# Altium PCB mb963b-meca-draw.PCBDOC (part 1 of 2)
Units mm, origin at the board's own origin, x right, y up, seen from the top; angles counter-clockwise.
Board outline 55.97 x 112.25 mm, 2 copper layers (Top, Bottom), stack 0.323 mm thick; 137 components, 131 nets, 523 pads, 261 vias.
Unrouted connection lines stored in the file: 17.
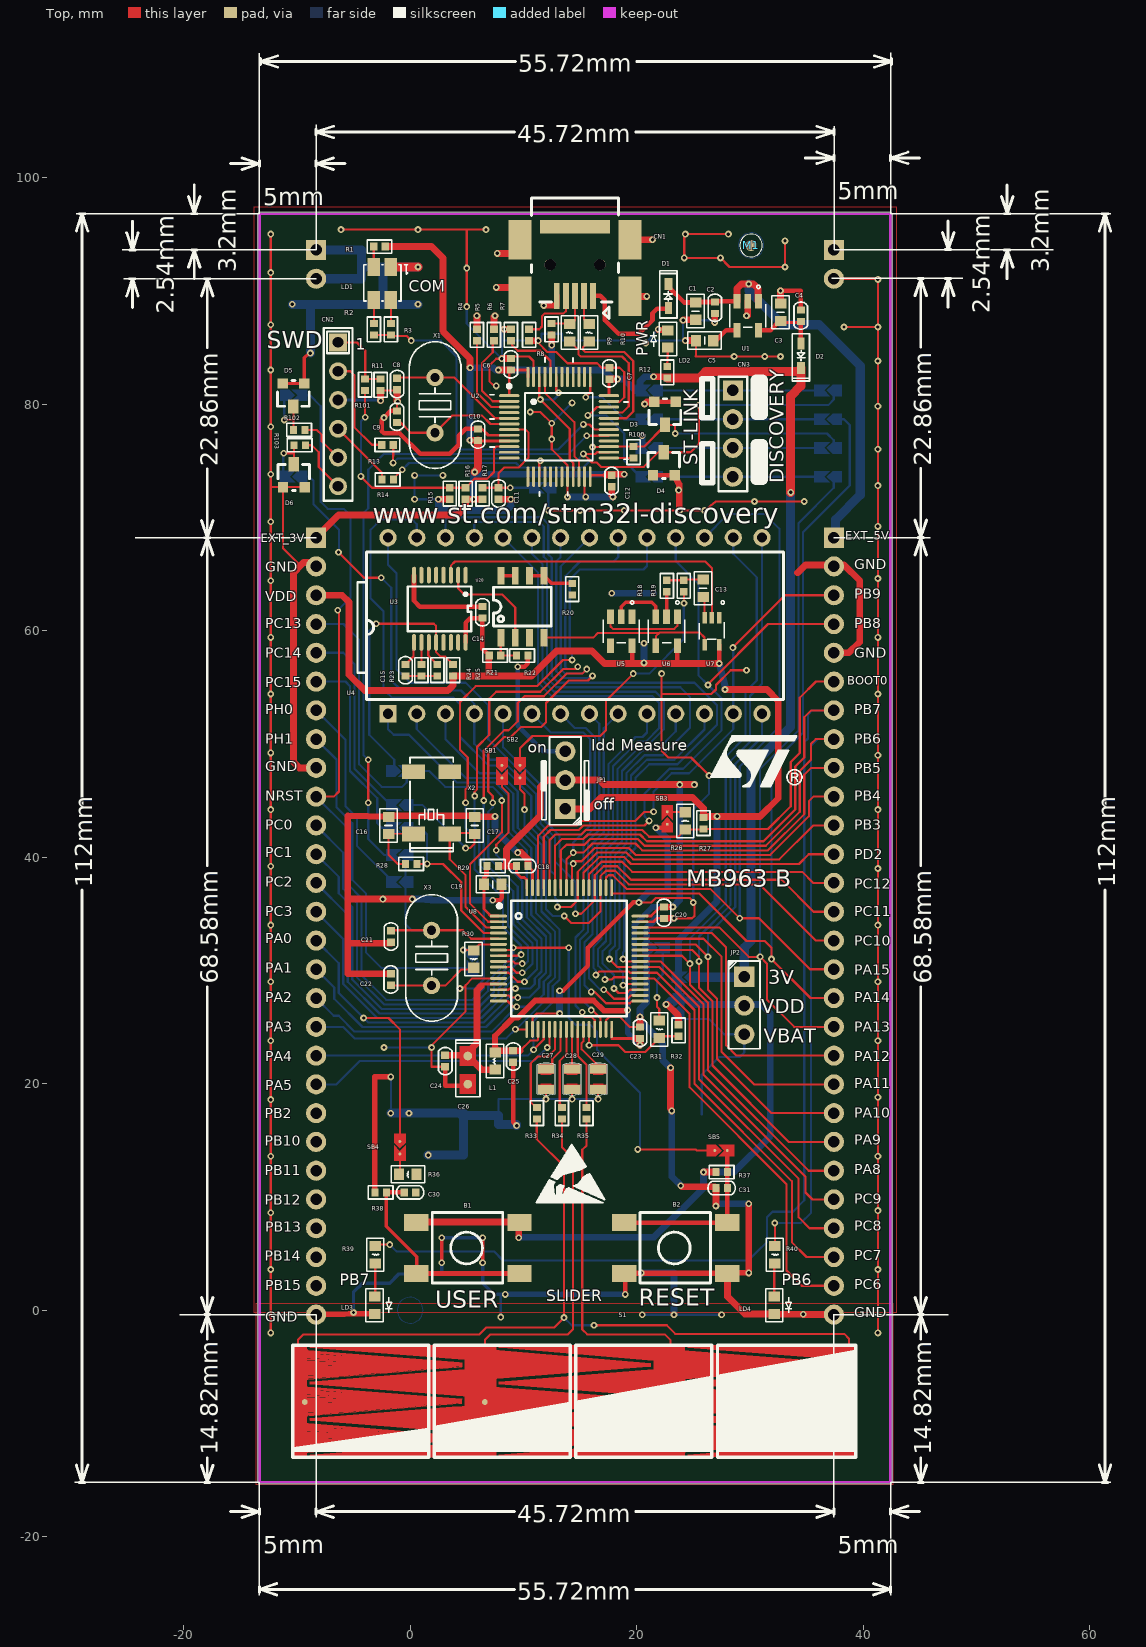
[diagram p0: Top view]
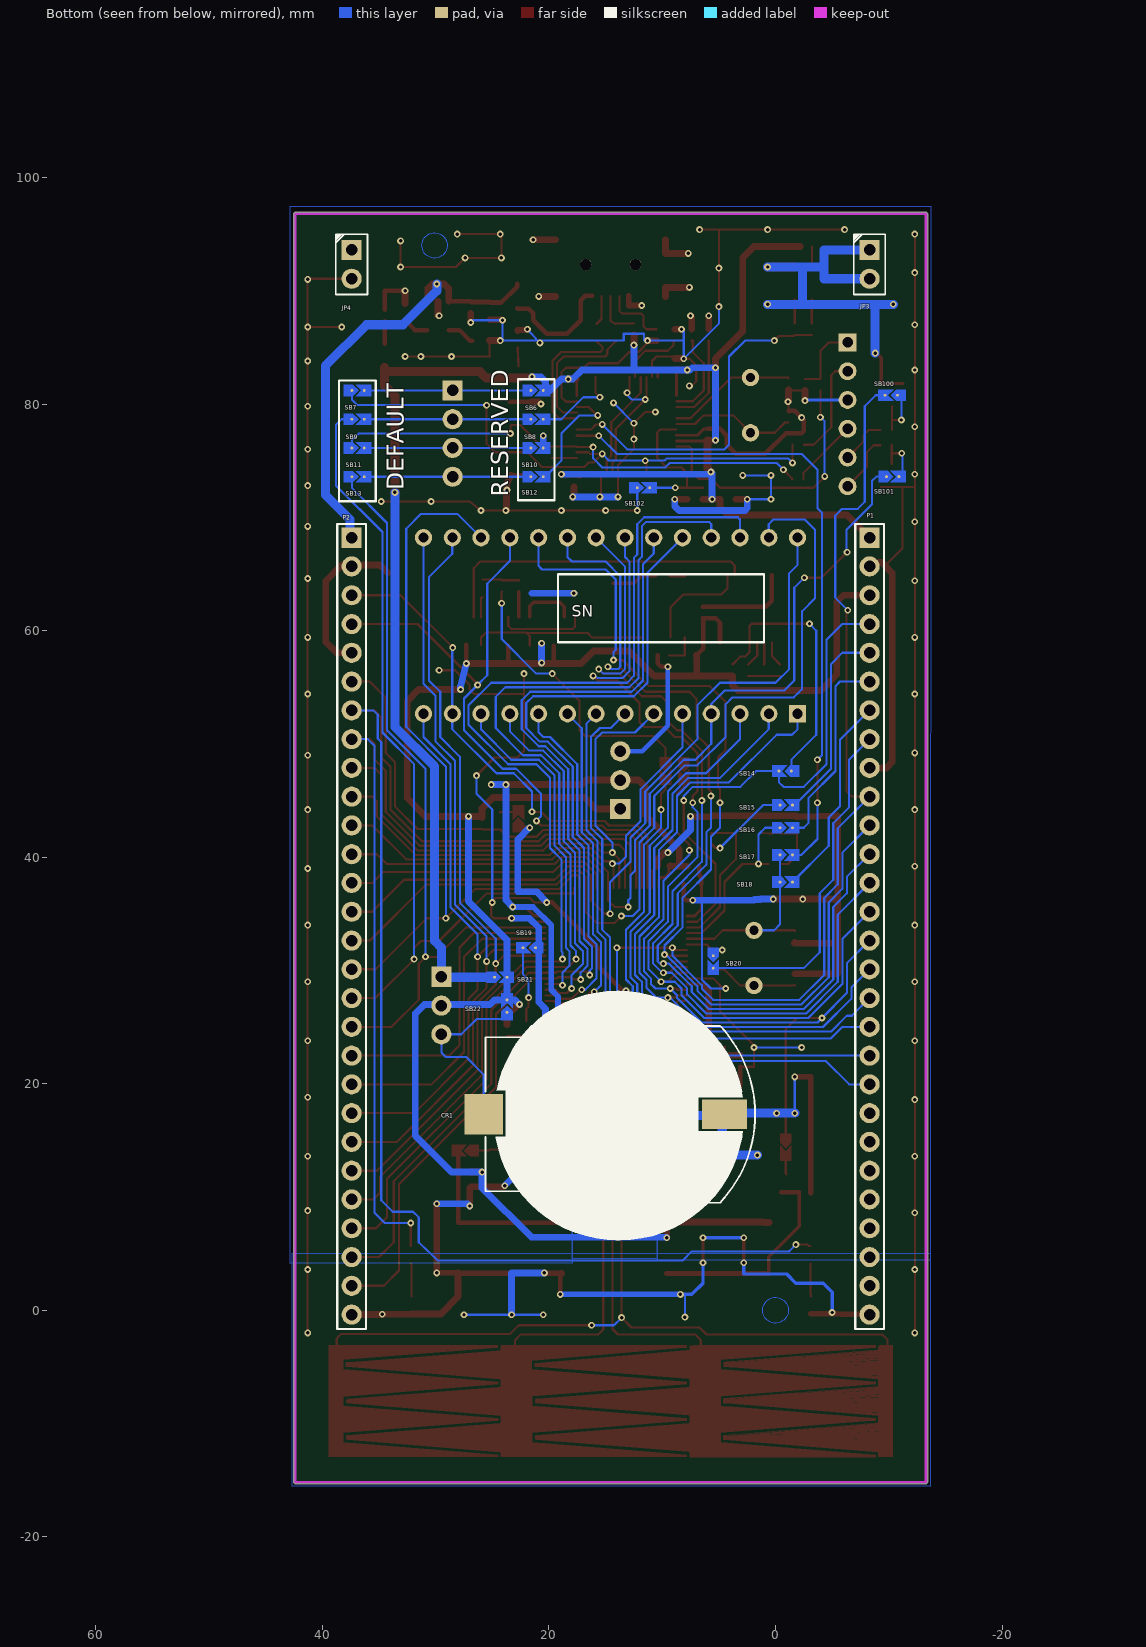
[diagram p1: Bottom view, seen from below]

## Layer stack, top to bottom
Top: signal copper 0.0343
Dielectric: dielectric 0.254, FR-4, Dk 4.3
Bottom: signal copper 0.0343

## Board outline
-13.427,-15.2 -13.3,-15.327 42.42,-15.327 42.547,-15.2 42.547,96.8 42.42,96.927 -13.3,96.927 -13.427,96.8

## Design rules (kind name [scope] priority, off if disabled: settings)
Clearance "'Default' PADS rule_18" [All] p1: gap=0.152
Clearance "'Default' PADS rule_15" [IsVia vs IsVia] p2: gap=0.152
ComponentClearance "'Default' PADS rule_12" [All] p1: gap=0.152 collisioncheckmode=3 verticalgap=0.254 showdistances=FALSE
FlightTimeFalling "'Default' PADS rule_10" [All] p1: maximum=10.00
FlightTimeRising "'Default' PADS rule_9" [All] p1: maximum=10.00
Length "'Default' PADS rule_5" [All] p1: maxlimit=1270 minlimit=0
MatchedLengths "'Default' PADS rule_11" [InNetClass('All Nets')] p1: tolerance=5.08 checknetsindiffpair=TRUE checkdiffpairvsdiffpair=TRUE checkothers=TRUE
MaxMinImpedance "'Default' PADS rule_8" [All] p1: minimum=50.00 maximum=150.0
ParallelSegment "'Default' PADS rule_7" [All] p1: limit=25.4 gap=5.08
ParallelSegment "'Default' PADS rule_6" [All] p2: limit=25.4 gap=5.08
PlaneClearance "Power Plane Clearance for CN2-1" [(Name='CN2-1') Or (Name='CN2-2') Or (Name='CN2-3') Or (Name='CN2-4') Or (Name='CN2-5') Or (Name='CN2-6')] p1: clearance=0.381 // PAD - Power Plane Clearance
PlaneClearance "'Default' PADS rule_14" [All] p2: clearance=0.25
PlaneConnect "Power Plane Connect Style - pads with no thermal" [(Name='CN1-6') Or (Name='CN1-7')] p1: planeconnectstyle=NoConnect reliefexpansion=0.508 reliefentries=4 reliefconductorwidth=0.254 reliefairgap=0.254 // PAD - No Thermal Connect Rule
PlaneConnect "Power Plane Connect Style - from global settings" [All] p2: planeconnectstyle=Relief reliefexpansion=0.508 reliefentries=2 reliefconductorwidth=0.3 reliefairgap=0.254
PolygonConnect [All] p1: connectstyle=Relief reliefconductorwidth=0.254 reliefentries=4 polygonreliefangle="90 Angle"
RoutingLayers "'Default' PADS rule_3" [All] p1: top layer_v5=TRUE bottom layer_v5=TRUE
RoutingPriority "'Default' PADS rule_2" [All] p1: routingpriority=3
RoutingTopology "'Default' PADS rule" [All] p1: topology=Shortest
RoutingVias "'Default' PADS rule_4" [All] p1: holewidth=0.3 width=0.6 viastyle="Through Hole" minholewidth=0.3 minwidth=0.6 maxholewidth=0.3 maxwidth=0.6
SMDToCorner "'Default' PADS rule_16" [All] p1: distance=60000
SMDToPlane "'Default' PADS rule_17" [All] p1: distance=60000
SilkscreenOverComponentPads [All] p1: minsilkscreentomaskgap=0.254
SolderMaskExpansion "Solder Mask Expansion from CAM settings" [All] p1: expansion=0.051
Width "'Default' PADS rule_13" [All] p1: maxlimit=0.5 minlimit=0.191 preferedwidth=0.191
21 further rules are at their usual default settings.

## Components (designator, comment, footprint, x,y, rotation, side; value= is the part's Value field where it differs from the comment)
B1 "SW4SMD" SW4SMD 0.56,7.745 r180 top
B2 "SW4SMD" SW4SMD 18.9,7.745 r180 top
C1 "0603C" 0603C 25.2,88.2 r90 top
C2 "0402C" 0402C 26.9,88.5 r90 top
C3 "0603C" 0603C 32.7,88.1 r90 top
C4 "0402C" 0402C 34.5,87.8 r270 top
C5 "0603C" 0603C 26,85.6 r0 top
C6 "0402C" 0402C 8.9,83.5 r270 top
C7 "0402C" 0402C 17.6,82.7 r270 top
C8 "0402C" 0402C -1.15,81.77 r90 top
C9 "0402C" 0402C -1.15,78.87 r270 top
C10 "0402C" 0402C 6,77.3 r270 top
C11 "0402C" 0402C 7.8,72.1 r90 top
C12 "0402C" 0402C 17.8,73.2 r270 top
C13 "0603C" 0603C 25.859,63.738 r270 top
C14 "0402C" 0402C 6.404,61.61 r270 top
C15 "0402C" 0402C -0.4,56.5 r270 top
C16 "0603C" 0603C -1.9,42.8 r90 top
C17 "0603C" 0603C 5.7,42.8 r90 top
C18 "0402C" 0402C 9.9,39.2 r180 top
C19 "0603C" 0603C 7.3,37.6 r0 top
C20 "0402C" 0402C 22.4,35.1 r90 top
C21 "0402C" 0402C -1.7,33 r90 top
C22 "0402C" 0402C -1.7,29.2 r270 top
C23 "0402C" 0402C 20.3,24.5 r90 top
C24 "0402C" 0402C 3.1,22 r90 top
C25 "0402C" 0402C 9.1,22.4 r90 top
C26 "CASE-A" CASE-A 5.1,21.2 r270 top
C27 "CAP0805" CAP0805 12,20.4 r90 top
C28 "CAP0805" CAP0805 14.3,20.4 r90 top
C29 "CAP0805" CAP0805 16.6,20.4 r90 top
C30 "0402C" 0402C 0,10.4 r180 top
C31 "0402C" 0402C 27.5,10.8 r0 top
CN1 "USB-MINI-B-SMD-A" USB-MINI-B-SMD-A 14.56,92.3 r0 top
CN2 "IDC6X1" IDC6X1 -6.362,85.439 r270 top
CN3 "HEADER4/2.54" HEADER4/2.54 28.5,81.2 r270 top
CR1 "BATT-1-CR2032" BATT-1-CR2032 13.2,17.3 r90 bottom
D1 "SOD323/A" SOD323/A 22.8,90.6 r270 top
D2 "SOD323/A" SOD323/A 34.5,83.2 r90 top
D3 "SOT23" SOT23 22.5,79.2 r180 top
D4 "SOT23" SOT23 22.4,74.7 r0 top
D5 "SOT23" SOT23 -10.299,80.821 r180 top
D6 "SOT23" SOT23 -10.262,73.653 r0 top
JP1 "SIP3/2.54" SIP3/2.54 13.7,46.8 r180 top
JP2 "SIP3/2.54" SIP3/2.54 29.5,26.9 r0 top
JP3 "SIP2/2.54" SIP2/2.54 -8.3,92.33 r180 bottom
JP4 "SIP2/2.54" SIP2/2.54 37.42,92.33 r180 bottom
L1 "0603L" 0603L 7.5,22 r270 top
LD1 "AV02-0501EN" AV02-0501EN -2.4,90.7 r180 top
LD2 "LED0603" LED0603 22.759,85.741 r90 top
LD3 "LED0603" LED0603 -3.139,0.441 r270 top
LD4 "LED0603" LED0603 32.141,0.441 r270 top
M1 "SMDPAD-T" SMDPAD-T 30.1,94 r0 top
P1 "HEAD28/2.54" HEAD28/2.54 -8.3,45.34 r270 bottom
P2 "HEAD28/2.54" HEAD28/2.54 37.42,45.34 r270 bottom
R1 "0402R" 0402R -2.7,93.9 r0 top
R2 "0402R" 0402R -3.2,86.6 r90 top
R3 "0402R" 0402R -1.7,86.6 r90 top
R4 "0402R" 0402R 5.9,86.1 r270 top
R5 "0402R" 0402R 7.4,86.1 r270 top
R6 "0402R" 0402R 8.9,86.1 r270 top
R7 "0402R" 0402R 10.5,86.1 r270 top
R8 "0402R" 0402R 12.5,86.6 r270 top
R9 "0603R" 0603R 14.1,86.3 r270 top
R10 "0603R" 0603R 15.8,86.3 r270 top
R11 "0402R" 0402R -2.6,81.7 r270 top
R12 "0402R" 0402R 22.7,82.8 r270 top
R13 "0402R" 0402R -2,76.4 r0 top
R14 "0402R" 0402R -1.974,73.329 r0 top
R15 "0402R" 0402R 3.5,72.1 r90 top
R16 "0402R" 0402R 4.9,72.1 r90 top
R17 "0402R" 0402R 6.4,72.1 r270 top
R18 "0402R" 0402R 22.659,63.938 r90 top
R19 "0402R" 0402R 24.159,63.938 r270 top
R20 "0402R" 0402R 14.316,63.66 r270 top
R21 "0402R" 0402R 7.5,57.8 r180 top
R22 "0402R" 0402R 9.9,57.8 r180 top
R23 "0402R" 0402R 1,56.5 r270 top
R24 "0402R" 0402R 2.4,56.5 r270 top
R25 "0402R" 0402R 3.8,56.5 r90 top
R26 "0603R" 0603R 24.3,43.2 r270 top
R27 "0402R" 0402R 25.9,43 r90 top
R28 "0402R" 0402R 0.1,39.4 r0 top
R29 "0402R" 0402R 7.3,39.2 r180 top
R30 "0603R" 0603R 5.6,31 r90 top
R31 "0603R" 0603R 22,24.8 r90 top
R32 "0402R" 0402R 23.7,24.7 r270 top
R33 "0402R" 0402R 11.185,17.4 r270 top
R34 "0402R" 0402R 13.4,17.4 r270 top
R35 "0402R" 0402R 15.569,17.4 r270 top
R36 "0603R" 0603R -0.2,12 r0 top
R37 "0402R" 0402R 27.5,12.2 r180 top
R38 "0402R" 0402R -2.6,10.4 r0 top
R39 "0603R" 0603R -3.08,4.9 r90 top
R40 "0603R" 0603R 32.2,4.9 r90 top
R100 "0402R" 0402R 19.733,75.749 r90 top
R101 "0402R" 0402R -3.965,81.703 r90 top
R102 "0402R" 0402R -9.787,77.715 r0 top
R103 "0402R" 0402R -9.748,76.364 r180 top
S1 "S1" S1 12.7,-8.1 r0 top
SB1 "JUMPER" JUMPER 8.1,47.6 r270 top
SB2 "JUMPER" JUMPER 9.7,47.6 r270 top
SB3 "JUMPER" JUMPER 22.7,43.4 r90 top
SB4 "JUMPER" JUMPER -0.9,14.4 r270 top
SB5 "JUMPER" JUMPER 27.4,14.1 r0 top
SB6 "JUMPER" JUMPER 21.1,81.2 r180 bottom
SB7 "JUMPER" JUMPER 36.9,81.2 r180 bottom
SB8 "JUMPER" JUMPER 21.1,78.66 r180 bottom
SB9 "JUMPER" JUMPER 36.9,78.66 r180 bottom
SB10 "JUMPER" JUMPER 21.1,76.12 r180 bottom
SB11 "JUMPER" JUMPER 36.9,76.12 r180 bottom
SB12 "JUMPER" JUMPER 21.1,73.58 r180 bottom
SB13 "JUMPER" JUMPER 36.9,73.58 r180 bottom
SB14 "JUMPER" JUMPER -0.9,47.6 r0 bottom
SB15 "JUMPER" JUMPER -0.9,44.6 r180 bottom
SB16 "JUMPER" JUMPER -0.9,42.6 r180 bottom
SB17 "JUMPER" JUMPER -0.9,40.2 r180 bottom
SB18 "JUMPER" JUMPER -0.9,37.8 r180 bottom
SB19 "JUMPER" JUMPER 21.7,32 r0 bottom
SB20 "JUMPER" JUMPER 5.5,30.8 r270 bottom
SB21 "JUMPER" JUMPER 24.3,29.4 r180 bottom
SB22 "JUMPER" JUMPER 23.7,26.8 r90 bottom
SB100 "JUMPER" JUMPER -10.276,80.773 r0 bottom
SB101 "JUMPER" JUMPER -10.295,73.594 r180 bottom
SB102 "JUMPER" JUMPER 11.703,72.614 r180 bottom
U1 "SOT-23-5L" SOT-23-5L 29.8,87.8 r0 top
U2 "LQFP48/0.5MM\9X9B" LQFP48/0.5MM\9X9B 10.3,73.6 r0 top
U3 "TSSOP16" TSSOP16 4.9,64.9 r180 top
U4 "GH08172-DIP28" GH08172-DIP28 14.56,60.43 r0 top
U5 "SOT-23-5L" SOT-23-5L 18.645,59.943 r0 top
U6 "SOT-23-5L" SOT-23-5L 22.645,59.943 r0 top
U7 "SOT323-5L" SOT323-5L 26.645,59.943 r0 top
U8 "QFP64" QFP64 7.8,34.8 r0 top
U20 "SO8" SO8 8.012,59.379 r0 top
X1 "HC-49A" HC-49A 2.2,79.9 r90 top
X2 "MC306-CRYSTAL" MC306-CRYSTAL 1.9,44.8 r90 top
X3 "HC-49A" HC-49A 1.9,31.1 r90 top

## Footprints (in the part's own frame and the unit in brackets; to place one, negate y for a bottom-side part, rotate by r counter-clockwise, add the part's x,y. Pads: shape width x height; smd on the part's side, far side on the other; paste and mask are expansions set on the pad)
0402C [mil]
  rect 25x27.56 smd: 1(-20,0) 2(20,0)
  silkscreen extent -48,-24 47,23
0402R [mil]
  rect 25x27.56 smd: 1(-20,0) 2(20,0)
  silkscreen extent -43,-23 43,23
0603C [mil]
  rect 35x40 smd: 1(-30,0) 2(30,0)
  silkscreen extent -58,-30 58,30
0603L [mil]
  rect 35x40 smd: 1(-30,0) 2(30,0)
  silkscreen extent -58,-30 58,30
0603R [mil]
  rect 35x40 smd: 1(-30,0) 2(30,0)
  silkscreen extent -58,-30 58,30
AV02-0501EN [mm]
  rect 1.1x1.6 smd: 1(-0.7,-1.4) 2(-0.7,1.5) 3(0.8,1.5) 4(0.8,-1.4)
  silkscreen extent -2.2,-1.6 1.7,1.6
BATT-1-CR2032 [mm]
  rect 3.6x3.4 smd: 1(0,12.55)
  rect 2.6x4 smd: 2(0,-8.7)
  silkscreen extent -7.81,-11.4 7.8,12.4
CAP0805 [mm]
  rect 0.8x1.4 smd: 1(-0.9,0) 2(0.9,0)
  Top region: -1.3,0.7 -0.5,0.7 -0.5,0.45 -0.4,0.45 -0.4,-0.45 -0.5,-0.45 -0.5,-0.7 -1.3,-0.7 -1.3,0.7
  Top region: 0.5,0.7 0.5,0.45 0.4,0.45 0.4,-0.45 0.5,-0.45 0.5,-0.7 1.3,-0.7 1.3,0.7 0.5,0.7
  silkscreen extent -1.41,-0.83 1.42,0.78
CASE-A [mil]
  round 30 smd: 1(-49,0) 2(49,0)
  Top region: -83,-28 -15,-28 -15,28 -83,28 -83,-28
  Top region: 15,-28 83,-28 83,28 15,28 15,-28
  silkscreen extent -105,-42 93,42
GH08172-DIP28 [mil]
  rect 60x60 hole 35: 1(-650,-305.91)
  round 60 hole 35: 2(-550,-305.91) 3(-450,-305.91) 4(-350,-305.91) 5(-250,-305.91) 6(-150,-305.91) 7(-50,-305.91) 8(50,-305.91) 9(150,-305.91) 10(250,-305.91) 11(350,-305.91) 12(450,-305.91) 13(550,-305.91) 14(650,-305.91) 15(650,305.91) 16(550,305.91) 17(450,305.91) 18(350,305.91) 19(250,305.91) 20(150,305.91) 21(50,305.91) 22(-50,305.91) 23(-150,305.91) 24(-250,305.91) 25(-350,305.91) 26(-450,305.91) 27(-550,305.91) 28(-650,305.91)
  silkscreen extent -756,-256 725,256
HC-49A [mil]
  round 60 hole 32: 1(-96.06,0) 2(96.06,0)
  silkscreen extent -220,-90 220,90
HEAD28/2.54 [mil]
  rect 70x70 hole 40: 1(-900,0)
  round 70 hole 40: 2(-800,0) 3(-700,0) 4(-600,0) 5(-500,0) 6(-400,0) 7(-300,0) 8(-200,0) 9(-100,0) 10(0,0) 11(100,0) 12(200,0) 13(300,0) 14(400,0) 15(500,0) 16(600,0) 17(700,0) 18(800,0) 19(900,0) 20(1000,0) 21(1100,0) 22(1200,0) 23(1300,0) 24(1400,0) 25(1500,0) 26(1600,0) 27(1700,0) 28(1800,0)
  silkscreen extent -948,-50 1850,50
HEADER4/2.54 [mil]
  rect 70x70 hole 40: 1(0,0)
  round 70 hole 40: 2(100,0) 3(200,0) 4(300,0)
  silkscreen extent -48,-50 350,50
IDC6X1 [mil]
  rect 62x62 hole 37: 1(0,0)
  round 62 hole 37: 2(100,0) 3(200,0) 4(300,0) 5(400,0) 6(500,0)
  silkscreen extent -50,-50 550,50
JUMPER [mil]
  round 10 smd: 1(-19.69,0) 2(23.62,0)
  Top region: -47.24,-19.68 -47.24,19.68 -15.75,19.68 3.94,0 -15.75,-19.68 -47.24,-19.68
  Top region: -5.91,19.68 13.78,0 -5.91,-19.68 47.24,-19.68 47.24,19.68 -5.91,19.68
LED0603 [mil]
  rect 35x40 smd: 1(-30,0) 2(30,0)
  silkscreen extent -58,-30 58,62
LQFP48/0.5MM\9X9B [mil]
  oval 71x10.13 smd: 1(-61,281.06) 12(-61,64.52) 25(285.46,64.53) 36(285.46,281.06)
  oval 71x10 smd: 2(-61,261.38) 3(-61,241.69) 4(-61,222.01) 5(-61,202.32) 6(-61,182.64) 7(-61,162.95) 8(-61,143.27) 9(-61,123.58) 10(-61,103.9) 11(-61,84.21) 26(285.46,84.21) 27(285.46,103.9) 28(285.46,123.58) 29(285.46,143.27) 30(285.46,162.95) 31(285.46,182.64) 32(285.46,202.32) 33(285.46,222.01) 34(285.46,241.69) 35(285.46,261.38)
  oval 10.13x71 smd: 13(3.96,-0.43) 24(220.5,-0.43) 37(220.5,346.02) 48(3.96,346.02)
  oval 10x71 smd: 14(23.65,-0.43) 15(43.33,-0.43) 16(63.02,-0.43) 17(82.7,-0.43) 18(102.39,-0.43) 19(122.07,-0.43) 20(141.76,-0.43) 21(161.44,-0.43) 22(181.13,-0.43) 23(200.81,-0.43) 38(200.81,346.02) 39(181.13,346.02) 40(161.44,346.02) 41(141.76,346.02) 42(122.07,346.02) 43(102.39,346.02) 44(82.7,346.02) 45(63.02,346.02) 46(43.33,346.02) 47(23.65,346.02)
  silkscreen extent -129,-69 354,414
MC306-CRYSTAL [mm]
  rect 1.3x2 smd: 1(-2.75,-1.6) 2(2.75,-1.6) 3(2.75,1.6) 4(-2.75,1.6)
  silkscreen extent -4.3,-1.9 4,1.9
QFP64 [mm]
  oval 1.5x0.25 smd: 1(0,0) 2(0,-0.5) 3(0,-1) 4(0,-1.5) 5(0,-2) 6(0,-2.5) 7(0,-3) 8(0,-3.5) 9(0,-4) 10(0,-4.5) 11(0,-5) 12(0,-5.5) 13(0,-6) 14(0,-6.5) 15(0,-7) 16(0,-7.5) 33(12.5,-7.5) 34(12.5,-7) 35(12.5,-6.5) 36(12.5,-6) 37(12.5,-5.5) 38(12.5,-5) 39(12.5,-4.5) 40(12.5,-4) 41(12.5,-3.5) 42(12.5,-3) 43(12.5,-2.5) 44(12.5,-2) 45(12.5,-1.5) 46(12.5,-1) 47(12.5,-0.5) 48(12.5,0)
  oval 0.25x1.5 smd: 17(2.5,-10) 18(3,-10) 19(3.5,-10) 20(4,-10) 21(4.5,-10) 22(5,-10) 23(5.5,-10) 24(6,-10) 25(6.5,-10) 26(7,-10) 27(7.5,-10) 28(8,-10) 29(8.5,-10) 30(9,-10) 31(9.5,-10) 32(10,-10) 49(10,2.5) 50(9.5,2.5) 51(9,2.5) 52(8.5,2.5) 53(8,2.5) 54(7.5,2.5) 55(7,2.5) 56(6.5,2.5) 57(6,2.5) 58(5.5,2.5) 59(5,2.5) 60(4.5,2.5) 61(4,2.5) 62(3.5,2.5) 63(3,2.5) 64(2.5,2.5)
  silkscreen extent -0.14,-8.84 11.33,1.35
S1 [mil]
  round 20 smd: 1(-866.14,0) 2(-240.16,0) 3(405.51,0)
  round 28 smd: 4(1025,0)
  Top region: -249.01,128.08 -213.15,-191.21 -202.12,-177.27 -201.1,-174.79 -201.03,-174.73 -198.84,-173.71 332.66,-131.08 335.88,-127.59 335.88,-115.82 333.02,-115.82 332.74,-115.81 -197.99,-73.83 -198.26,-73.82 -199.3,-73.82 -200.86,-73.45 -202.12,-72.82 -202.12,-50.64 -201.75,-49.08 -201.64,-48.86 -200.08,-47.3 -199.73,-47.12 -198.45,-46.76 332.66,-4.08 335.88,-0.59 335.88,7.09 332.81,10.57 327.96,11.17 327.8,11.19 -190.1,52.18 -190.14,52.18 -199.86,53.07 -202.02,54.08 -202.12,54.18 -202.12,76.73 -201.1,79.21 -201.03,79.27 -198.84,80.29 329.21,122.17 330.16,122.26 336.48,122.78 336.48,133.98 -210.18,180.92 -213.71,180.31 -249.01,128.08
  Top region: -201.32,195.38 -217.47,196.46 -848.03,196.46 -848.03,190.16 -846.85,188.98 -309.84,146.46 -309.84,114.57 -848.03,70.47 -848.03,62.6 -846.46,62.2 -314.96,20.08 -311.02,19.69 -309.84,19.29 -309.84,-12.99 -319.29,-14.17 -352.76,-16.93 -848.03,-56.69 -848.03,-64.17 -846.85,-64.57 -842.91,-64.96 -832.68,-65.75 -524.02,-90.16 -309.84,-107.09 -309.84,-140.55 -842.52,-183.07 -846.85,-183.46 -848.03,-184.65 -848.03,-191.34 -201.32,-191.34 -201.32,195.38
  Top region: 454.28,195.58 452.32,197.54 -191.34,197.64 -191.34,189.37 -187.4,188.98 -182.28,188.58 346.46,142.91 346.46,113.39 -190.55,70.87 -191.34,70.87 -191.34,62.2 345.65,19.71 345.67,19.69 345.67,-12.6 -191.34,-56.3 -191.34,-64.57 75.2,-85.43 346.06,-106.69 346.06,-140.16 -191.38,-183.06 -191.34,-189.37 -191.24,-191.02 454.28,-191.02 454.28,195.58
  Top region: 408.81,115.37 454.28,-177.77 455.3,-175.29 455.37,-175.23 457.56,-174.21 989.06,-131.58 992.28,-128.09 992.28,-116.32 989.42,-116.32 989.14,-116.31 458.41,-74.33 458.14,-74.32 457.1,-74.32 455.54,-73.95 454.28,-73.32 454.28,-51.14 454.65,-49.58 454.76,-49.36 456.32,-47.8 456.67,-47.62 457.95,-47.26 989.06,-4.58 992.28,-1.09 992.28,6.59 989.21,10.07 984.36,10.67 984.2,10.69 466.3,51.68 466.26,51.68 456.54,52.57 454.38,53.58 454.28,53.68 454.28,76.23 455.3,78.71 455.37,78.77 457.56,79.79 970.4,120.78 970.55,120.79 986.62,122.13 992.88,122.68 992.88,137.58 980.39,138.58 446.2,180.44 442.72,179.82 408.81,115.37
  Top region: 1051.97,197.24 464.57,197.24 464.57,188.98 1002.73,146.87 1003.15,146.6 1003.15,114.17 464.17,70.47 464.17,61.81 1001.97,18.9 1001.97,-13.39 464.17,-57.09 464.17,-64.96 1002.76,-107.48 1002.76,-140.16 464.17,-183.46 464.17,-190.55 1052.07,-190.55 1051.97,197.24
  Top lines w1: -907.32,-188.92 -897.82,-188.92 ; -907.32,-187.92 -904.32,-187.92 ; -907.32,-185.92 -907.21,-186.85 -903.73,-189.92 -863.32,-189.92 -859.82,-186.42 -859.82,-183.92 ; -907.32,195.83 -907.32,-190.92 -858.32,-190.92 -858.32,-175.95 -856.51,-173.98 -319.84,-130.94 ; -906.98,195.83 -861.82,195.83 -858.32,192.33 -858.32,182.82 -855.1,179.33 -347.84,139.45 -330.82,138.08 -320.08,137.01 -320.06,122.87 -338.92,121.5 -347.2,120.77 -856.51,79.84 -858.32,77.88 -858.32,53.06 -856.49,52.58 -320.26,10.52 -319.82,10.08 -319.82,-4.04 -319.97,-4.15 -330.18,-4.95 -330.46,-4.96 -856.51,-47.16 -858.32,-49.13 -858.32,-72.99 -853.23,-74.53 -319.82,-116.42 -319.82,-130.92 ; -906.82,195.08 -906.32,195.58 ; -905.82,-190.42 -905.32,-189.92 -906.82,-189.42 -906.82,-189.92 -903.32,-190.42 -905.82,-188.42 ; -865.32,-174.42 -845.82,-171.42 ; -864.32,-47.92 -808.32,-41.42 ; -863.82,-190.42 -858.82,-190.42 -858.82,-187.42 -861.82,-187.42 -861.82,-189.92 -859.32,-189.92 -859.32,-187.92 -861.32,-187.92 -861.32,-189.42 -859.82,-189.42 -859.82,-188.42 -860.82,-188.42 ; -860.82,-173.42 -843.32,-172.42 ; -859.82,-175.42 -855.82,-171.92 ; -859.82,-46.42 -855.32,-46.42 ; -859.32,-175.42 -856.82,-172.92 ; -859.32,77.58 -857.32,79.58 ; -858.82,-175.42 -856.32,-171.92 ; -858.82,-73.42 -855.82,-74.92 ; -858.82,-48.92 -857.82,-46.92 ; -858.32,80.58 -854.32,80.58 ; -857.82,-174.42 -857.32,-172.92 ; -825.32,-44.42 -804.32,-42.42 ; -651.32,-90.92 -337.32,-115.92 ; -621.32,-103.42 -529.82,-110.92 ; -615.82,-103.42 -525.82,-111.92 ; -588.32,157.58 -360.32,139.58 -325.32,136.58 ; -588.22,30.78 -360.22,12.78 -325.22,9.78 ; -586.92,-96.52 -358.92,-114.52 -323.92,-117.52 ; -586.82,-149.42 -578.32,-150.92 ; -582.32,-150.92 -575.82,-150.92 ; -512.82,-145.92 -492.32,-143.42 ; -504.32,-144.92 -492.82,-143.42 -501.82,-144.42 ; -502.82,-144.92 -491.82,-143.92 ; -352.32,138.58 -323.32,136.58 ; -352.22,11.78 -323.22,9.78 ; -350.92,-115.52 -321.92,-117.52 ; -339.32,138.58 -329.32,137.58 ; -339.22,11.78 -329.22,10.78 ; -337.92,-115.52 -327.92,-116.52 ; -329.32,-116.42 -321.32,-116.92 -321.32,-130.42 ; -329.32,122.58 -323.32,123.58 ; -329.22,-4.22 -323.22,-3.22 ; -328.32,123.58 -320.32,123.58 ; -328.22,-3.22 -320.22,-3.22 ; -327.92,-131.52 -321.92,-130.52 ; -325.32,-117.92 -323.82,-118.42 ; -320.82,-130.42 -320.82,-116.92 ; -320.32,135.58 -320.32,136.58 ; -320.22,8.78 -320.22,9.78 ; -319.84,-130.94 -319.82,-130.92
  Top lines w2: -888.82,194.98 -864.72,194.98
  Top lines w5: -905.32,193.08 -864.32,192.58 ; -862.32,82.58 -825.32,84.58 ; -862.22,-44.22 -825.22,-42.22 ; -861.82,181.58 -855.82,176.08 ; -861.32,79.58 -857.32,82.58 ; -860.82,181.58 -857.32,177.58 ; -859.42,-170.02 -822.42,-168.02 ; -749.32,91.58 -727.32,94.58 ; -749.22,-35.22 -727.22,-32.22 ; -748.32,90.58 -715.32,93.58 ; -748.22,-36.22 -715.22,-33.22 ; -747.92,-162.52 -725.92,-159.52 ; -746.92,-163.52 -713.92,-160.52 ; -720.32,93.58 -677.32,100.58 ; -720.22,-33.22 -677.22,-26.22 ; -718.92,-160.52 -675.92,-153.52 ; -717.32,95.58 -685.32,99.58 ; -717.22,-31.22 -685.22,-27.22 ; -716.32,93.58 -640.32,99.58 ; -716.22,-33.22 -640.22,-27.22 ; -715.92,-158.52 -683.92,-154.52 ; -714.92,-160.52 -638.92,-154.52 ; -643.32,101.58 -611.32,104.58 ; -643.22,-25.22 -611.22,-22.22 ; -641.92,-152.52 -609.92,-149.52 ; -639.32,99.58 -599.32,103.58 ; -639.22,-27.22 -599.22,-23.22 ; -637.92,-154.52 -597.92,-150.52 ; -607.82,-103.42 -523.82,-109.42 ; -604.32,102.58 -561.32,108.58 ; -604.22,-24.22 -561.22,-18.22 ; -602.92,-151.52 -559.92,-145.52 ; -595.32,102.58 -547.32,106.58 ; -595.22,-24.22 -547.22,-20.22 ; -556.32,109.58 -517.32,113.58 ; -556.22,-17.22 -517.22,-13.22 ; -554.92,-144.52 -515.92,-140.52 ; -550.32,106.58 -513.32,112.58 ; -550.22,-20.22 -513.22,-14.22 ; -540.32,107.58 -527.32,111.58 ; -540.22,-19.22 -527.22,-15.22 ; -538.92,-146.52 -525.92,-142.52 ; -536.32,107.58 -492.32,114.58 ; -536.22,-19.22 -492.22,-12.22 ; -521.32,108.58 -493.32,111.58 ; -521.22,-18.22 -493.22,-15.22 ; -516.32,109.58 -473.32,116.58 ; -516.22,-17.22 -473.22,-10.22 ; -514.92,-144.52 -471.92,-137.52 ; -500.32,110.58 -435.32,119.58 ; -500.22,-16.22 -435.22,-7.22 ; -490.32,112.58 -462.32,115.58 ; -490.22,-14.22 -462.22,-11.22 ; -488.92,-141.52 -460.92,-138.52 ; -483.32,112.58 -462.32,113.58 -410.32,119.58 ; -483.22,-14.22 -462.22,-13.22 -410.22,-7.22 ; -481.92,-141.52 -460.92,-140.52 -408.92,-134.52 ; -464.32,114.58 -411.32,122.58 ; -464.22,-12.22 -411.22,-4.22 ; -462.92,-139.52 -409.92,-131.52 ; -438.32,115.58 -403.32,118.58 ; -438.22,-11.22 -403.22,-8.22 ; -436.92,-138.52 -401.92,-135.52 ; -436.32,117.58 -401.32,119.58 ; -436.22,-9.22 -401.22,-7.22 ; -434.92,-136.52 -399.92,-134.52 ; -433.32,117.58 -370.32,122.58 ; -433.22,-9.22 -370.22,-4.22 ; -432.32,120.58 -376.32,122.58 ; -432.22,-6.22 -376.22,-4.22 ; -431.92,-136.52 -368.92,-131.52 ; -430.92,-133.52 -374.92,-131.52 ; -426.32,118.58 -349.32,125.58 ; -426.22,-8.22 -349.22,-1.22 ; -424.92,-135.52 -347.92,-128.52 ; -400.32,118.58 -368.32,121.58 ; -400.22,-8.22 -368.22,-5.22 ; -398.92,-135.52 -366.92,-132.52 ; -363.32,123.58 -335.32,125.58 ; -363.22,-3.22 -335.22,-1.22 ; -361.92,-130.52 -333.92,-128.52 ; -346.32,125.58 -370.32,121.58 -325.32,125.58 ; -346.22,-1.22 -370.22,-5.22 -325.22,-1.22 ; -344.92,-128.52 -368.92,-132.52 -323.92,-128.52 ; -324.32,125.58 -324.32,134.58 ; -324.22,-1.22 -324.22,7.78 ; -322.92,-128.52 -322.92,-119.52 ; -322.32,125.58 -322.32,134.58 ; -322.22,-1.22 -322.22,7.78
  Top lines w10: -902.32,-185.42 -902.32,190.58 ; -894.32,-186.42 -894.32,190.58 ; -886.32,-186.42 -886.32,190.58 ; -880.32,-186.42 -880.32,190.58 ; -878.32,157.58 -329.32,127.58 ; -878.22,30.78 -329.22,0.78 ; -876.92,-96.52 -327.92,-126.52 ; -874.32,-185.42 -874.32,190.58 ; -872.32,-88.42 -501.82,-117.92 ; -872.32,165.58 -325.32,128.58 ; -872.22,38.78 -325.22,1.78 ; -868.32,-185.42 -868.32,190.58 ; -867.32,131.58 -814.32,129.58 ; -867.22,4.78 -814.22,2.78 ; -866.32,171.58 -816.32,166.58 ; -866.22,44.78 -816.22,39.78 ; -865.92,-122.52 -812.92,-124.52 ; -864.92,-82.52 -814.92,-87.52 ; -864.82,-113.92 -444.82,-131.42 ; -864.32,148.58 -360.32,124.58 ; -864.32,175.58 -328.32,131.58 ; -864.22,21.78 -360.22,-2.22 ; -864.22,48.78 -328.22,4.78 ; -863.32,-185.42 -863.32,190.58 ; -863.32,139.58 -392.32,121.58 ; -863.22,12.78 -392.22,-5.22 ; -862.92,-105.52 -358.92,-129.52 ; -862.92,-78.52 -326.92,-122.52 ; -862.32,85.58 -751.32,92.58 ; -862.32,102.58 -637.32,102.58 ; -862.22,-41.22 -751.22,-34.22 ; -862.22,-24.22 -637.22,-24.22 ; -861.32,108.58 -585.32,106.58 ; -861.32,123.58 -485.32,114.58 ; -861.32,133.58 -455.32,118.58 ; -861.22,-18.22 -585.22,-20.22 ; -861.22,-3.22 -485.22,-12.22 ; -861.22,6.78 -455.22,-8.22 ; -860.92,-168.52 -749.92,-161.52 ; -860.92,-151.52 -635.92,-151.52 ; -860.32,115.58 -549.32,111.58 ; -860.22,-11.22 -549.22,-15.22 ; -859.92,-145.52 -583.92,-147.52 ; -859.92,-130.52 -483.92,-139.52 ; -859.92,-120.52 -453.92,-135.52 ; -858.92,-138.52 -547.92,-142.52 ; -858.32,94.58 -705.32,97.58 ; -858.22,-32.22 -705.22,-29.22 ; -856.92,-159.52 -703.92,-156.52 ; -835.82,-92.42 -616.32,-103.92 ; -819.82,-88.42 -770.32,-91.42 ; -582.32,-146.42 -514.82,-141.92 ; -514.82,-141.42 -490.32,-138.42 ; -460.82,-131.92 -429.32,-130.92
  silkscreen extent -908,-192 1049,198
SIP2/2.54 [mil]
  rect 70x70 hole 40: 1(0,50)
  round 70 hole 40: 2(0,-50)
  silkscreen extent -55,-105 55,105
SIP3/2.54 [mil]
  rect 70x70 hole 40: 1(0,100)
  round 70 hole 40: 2(0,0) 3(0,-100)
  silkscreen extent -55,-150 55,155
SMDPAD-T [mil]
  round 39 smd: 1(0,0)
  silkscreen extent -39,-39 39,39
SO8 [mil]
  rect 24x60 smd: 1(0,0) 2(50,0) 3(100,0) 4(150,0) 5(150,215) 6(100,215) 7(50,215) 8(0,215)
  silkscreen extent -25,40 175,175
SOD323/A [mm]
  rect 1.06x0.6 smd: 1(2.14,0)
  rect 1.06x0.7 smd: 2(0,0)
  silkscreen extent -1.17,-0.76 3,0.76
SOT23 [mil]
  rect 36x36 smd: 1(-37.5,-39) 2(37.5,-39)
  rect 36x50 smd: 3(0,41)
  silkscreen extent -55,-50 55,40
SOT323-5L [mm]
  rect 0.4x1 smd paste+0.1 mask+0.135: 1(0.65,1.2) 2(0,1.2) 3(-0.65,1.2) 4(-0.65,-1.2) 5(0.65,-1.2)
  silkscreen extent -1.1,-0.7 1.1,2.69
SOT-23-5L [mm]
  rect 0.6x1.27 smd: 1(0.95,1.27) 2(0,1.27) 3(-0.95,1.27) 4(-0.95,-1.27) 5(0.95,-1.27)
  silkscreen extent -1.6,-1 1.6,2.69
SW4SMD [mil]
  rect 85x60 smd: 1(0,0) 2(-358.27,0) 3(0,177.17) 4(-358.27,177.17)
  silkscreen extent -300,-35 -55,210
TSSOP16 [mil]
  oval 14x58 smd: 1(0,0) 2(25.59,0) 3(51.18,0) 4(76.77,0) 5(102.36,0) 6(127.95,0) 7(153.54,0) 8(179.13,0) 9(179.13,234) 10(153.54,234) 11(127.95,234) 12(102.36,234) 13(76.77,234) 14(51.18,234) 15(25.59,234) 16(0,234)
  silkscreen extent -20,40 201,195
USB-MINI-B-SMD-A [mm]
  rect 0.508x2.3 smd: 1(1.597,-2.75) 2(0.797,-2.75) 3(-0.003,-2.75) 4(-0.803,-2.75) 5(-1.603,-2.75)
  round 1 hole 1 unplated: 6(2.194,0) 7(-2.2,0)
  rect 2x3.5 smd: 8(-4.853,-2.8) 9(4.847,-2.8) 10(4.847,2.2) 11(-4.853,2.2)
  rect 6.2x1.2 smd: 12(0,3.35)
  silkscreen extent -3.85,-4.76 3.85,5.9

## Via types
v1: diameter 0.6, hole 0.3, Top to Bottom, 261 vias

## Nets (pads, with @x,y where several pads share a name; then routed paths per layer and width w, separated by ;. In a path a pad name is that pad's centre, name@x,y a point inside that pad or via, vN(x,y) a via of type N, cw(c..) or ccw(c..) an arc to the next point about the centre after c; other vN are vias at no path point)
3V: C6.2 C7.2 C10.2 C12.1 D2.2 JP2.1 P1.1 R1.2 R8.2 R12.2 R16.1 R17.2 SB6.2 SB21.1 U2.1 U2.9 U2.24 U2.36 U2.48 | length 174.3
  Top w0.25: C10.2@6,76.739 U2.9@8.751,76.739 ; U2.1@8.751,80.739 8.751,82.843 C6.2@8.9,82.992 10.401,82.992 U2.48@10.401,82.389 ; U2.24@15.901,73.589 16.02,73.708 17.3,73.708 C12.1@17.8,73.708 ; U2.36@17.551,80.739 17.551,82.143 C7.2@17.6,82.192
  Top w0.6: P1.1@-8.3,68.2 -6.3,70.2 4.2,70.2 4.9,70.9 R16.1@4.9,71.592 v1(5.6,71.592) R17.2@6.4,71.592 ; R1.2@-2.192,93.9 1.9,93.9 2.9,92.9 2.9,86.4 5.3,84 v1(5.3,83.2) ; v1(5.3,76.8) C10.2@5.939,76.8 ; v1(7.8,83) 8.892,83 C6.2@8.9,82.992 ; v1(12.5,85.2) 12.5,86 12.454,86.046 R8.2@12.5,86.092 ; 17.3,73.708 17.392,73.8 v1(18.9,73.8) ; C7.2@17.6,82.192 17.608,82.2 v1(18.3,82.2) ; v1(21.5,82.4) 22.592,82.4 R12.2@22.7,82.292
  Top w0.7: v1(5.7,74) 6,74.3 6,76.739 C10.2@6,76.792
  Top w0.8: R12.2@22.7,82.292 25.532,82.292 26.1,82.86 ; 32.761,82.86 26.1,82.86 ; v1(33.6,72.2) 33.6,80.7 34.5,81.6 D2.2@34.5,82.86 ; D2.2@34.5,83.2 D2.2@34.5,82.86 ; 26.1,82.86 33.523,82.86 D2.2@34.5,82.86
  Bottom w0.6: v1(5.3,76.8) v1(5.3,83.2) 7.355,83.2 7.555,83 v1(7.8,83) 12.5,83 ; v1(5.6,71.592) v1@5.6,73.8 ; v1(5.7,74) 5.6,73.9 v1@5.6,73.8 ; v1(12.5,85.2) 12.5,83 ; v1(18.9,73.8) v1@5.6,73.8 ; SB6.2@20.5,81.2 20.3,81.2 ; v1(21.5,82.4) 20.7,82.4 20.3,82 20.3,81.367 20.3,81.2 ; 12.5,83 17.1,83 17.9,82.2 v1(18.3,82.2) 18.9,82.2 19.9,81.2 20.3,81.2
  Bottom w0.8: SB21.1@24.8,29.4 29.46,29.4 JP2.1@29.5,29.44 29.5,32 30.1,32.6 30.1,48 33.6,51.5 v1(33.6,72.2)
5V: C1.2 C2.2 D1.2 P2.1 U1.1 U1.3 | length 40.7
  Top w0.4: D1.2@22.8,90.6 22.8,90.362 24.2,88.962 C1.2@25.2,88.962 25.246,89.008 C2.2@26.9,89.008 26.962,89.07 U1.3@28.85,89.07
  Top w0.6: U1.3@28.85,89.07 28.85,90.2 29.25,90.6 v1(29.9,90.6) 30.3,90.6 30.7,90.2 30.7,89.12 U1.1@30.75,89.07
  Bottom w0.8: v1(29.9,90.6) 29.9,90 32.9,87 36.1,87 39.74,83.36 39.74,71.98 37.56,69.8 37.56,68.34 P2.1@37.42,68.2
$$$1: CN2.5 R102.2 | length 4.3
  Top w0.191: R102.2@-9.279,77.715 -8.23,77.715 -7.792,77.277 -7.792,76.709 CN2.5@-6.362,75.279
$$$2: R100.1 U2.25 | length 2.2
  Top w0.191: U2.25@17.551,75.239 17.553,75.241 R100.1@19.733,75.241
$$$3: CN1.1 D1.1 | length 10.3
  Top w0.4: CN1.1@16.157,89.55 16.8,89.55 17.2,89.15 17.2,87.4 18.4,86.2 20.2,86.2 21.4,87.4 21.4,88 21.8,88.4 22.74,88.4 D1.1@22.8,88.46
$$$4: CN2.6 R103.1 | length 5.1
  Top w0.191: R103.1@-9.24,76.364 -8.678,76.364 -8.063,75.749 -8.063,74.44 CN2.6@-6.362,72.739
$$$5: U3.2 U20.2 | length 9.6
  Top w0.191: U3.2@4.25,64.9 4.25,63.711 4.78,63.181 8.146,63.181 9.282,62.045 U20.2@9.282,59.379
AIN_1: R15.2 R16.2 R101.1 U2.10 | length 24
  Top w0.191: v1(-4.339,73.61) -4.339,73.589 -3.358,72.608 R15.2@3.5,72.608 R16.2@4.9,72.608 5.692,73.4 6.8,73.4 7.4,74 7.4,76.039 7.6,76.239 U2.10@8.751,76.239 ; v1(-3.967,78.84) -3.967,81.193 R101.1@-3.965,81.195
  Bottom w0.191: v1(-4.339,73.61) -4.339,78.468 v1(-3.967,78.84)
BOOT0: P2.6 R26.2 R27.1 U8.60 | length 40.8
  Top w0.191: U8.60@12.3,37.3 12.3,41.5 12.8,42 15.1,42 15.5,42.4 20.5,42.4 21.1,41.8 23.662,41.8 R26.2@24.3,42.438 25.846,42.438 R27.1@25.9,42.492 31.6,42.492 33.6,44.492 33.6,48.4 34.4,49.2 34.4,54.071 35.829,55.5 P2.6@37.42,55.5
GND: B2.3 B2.4 C1.1 C2.1 C3.2 C4.1 C5.1 C6.1 C7.1 C8.1 C9.1 C10.1 C11.1 C12.2 C13.2 C14.1 C16.2 C17.2 C18.1 C19.2 C20.1 C21.1 C22.1 C23.2 C24.1 C25.1 C26.2 C27.1 C28.1 C29.1 C31.1 CN1.5 CN1.8 CN1.9 CN1.10 CN1.11 CN1.12 CN2.3 CR1.2 D3.1 D3.2 D4.1 D4.2 D5.1 D5.2 D6.1 D6.2 JP3.1 JP3.2 JP4.1 JP4.2 LD1.1 LD2.2 LD3.2 LD4.2 P1.2 P1.9 P1.28 P2.2 P2.5 P2.28 R4.1 R5.1 R6.1 R7.2 R11.2 R15.1 R20.2 R38.1 SB3.1 SB10.2 SB19.1 SB102.1 U1.2 U2.8 U2.20 U2.23 U2.35 U2.47 U3.8 U5.1 U5.2 U6.3 U7.3 U8.12 U8.18 U8.31 U8.47 U8.63 | length 863.6
  Top w0.191: v1(-12.3,-2) v1(-12.3,3.6) v1(-12.3,8.6) v1(-12.3,13.6) v1(-12.3,18.6) v1(-12.3,23.8) v1(-12.3,29) v1(-12.3,34) v1(-12.3,39.2) v1(-12.3,44.2) v1(-12.3,49.2) v1(-12.3,54.4) v1(-12.3,59.4) v1(-12.3,64.4) v1(-12.3,69.6) -12.3,72.662 ; v1(-12.3,95) v1(-12.3,91.6) v1(-12.3,87) v1(-12.3,83) v1(-12.3,78) v1(-12.3,73.8) -12.3,72.662 ; -9.569,65.831 -9.78,65.831 -11.215,67.266 D6.1@-11.215,72.662 ; D6.2@-9.31,72.662 D6.1@-11.215,72.662 ; v1(-6.1,95.4) v1(0.7,95.4) 5,95.4 ; R11.2@-2.6,81.192 C8.1@-1.15,81.192 ; C9.1@-1.15,79.378 -1.15,80.2 v1@-1.15,80.25 ; C24.1@3.1,21.492 1.9,21.492 v1(1.9,23.2) 1.9,23.4 4.9,26.4 4.9,28.4 4.9,28.7 ; v1(4.4,28.4) 4.6,28.4 4.9,28.7 ; C26.2@4.9,19.8 5.1,19.8 C26.2@5.1,19.955 ; v1(5,88.6) v1(5,92) 5,95.4 ; v1(6.7,95.4) 5,95.4 ; v1(7.6,81.6) 7.4,81.6 7,82 7,83.4 7.6,84 v1(8.1,84) ; U8.12@7.8,29.3 5.5,29.3 4.9,28.7 ; v1(10.6,79.3) 11.5,79.3 v1(12.5,78.3) v1(12.5,76.9) 12.5,76.001 13.901,74.6 U2.20@13.901,73.589 v1@13.901,71.801 ; U8.18@10.8,24.8 10.8,25.802 11.198,26.2 v1(13.2,26.2) ; v1(11.3,85.6) 11.3,85.4 12.1,84.6 12.9,84.6 13.9,83.6 16.508,83.6 16.9,83.208 C7.1@17.6,83.208 18.5,83.208 18.9,82.808 18.9,80.6 18.5,80.2 17.59,80.2 U2.35@17.551,80.239 ; v1(12,18.641) C27.1@12,19.5 ; v1(12.2,70.6) v1(15,70.6) v1(18.9,70.6) v1(23.8,70.6) v1(26,70.6) 27,71.4 v1(30.4,71.4) v1(34.8,71.4) ; v1(14.3,18.641) C28.1@14.3,19.5 ; U2.23@15.401,73.589 15.401,71.899 v1(15.5,71.8) ; v1(16.6,18.641) C29.1@16.6,19.5 ; 17.3,25.6 17.3,25.604 17.6,25.904 18.504,25.904 19.4,25.008 C23.2@20.3,25.008 ; v1(20.2,36) 21.3,36 21.7,36.4 24.7,36.4 v1@25,36.1 ; v1(22.2,56.2) 22.2,54.4 ; 22.8,34.594 22.806,34.6 ; v1(23.3,34.6) 24.9,34.6 25.1,34.8 v1@25.1,36 ; v1(23.9,11) 23.904,11 v1@24.004,10.9 ; C5.1@25.238,85.6 25.238,84.238 25.2,84.2 v1(28.6,84.2) v1(31.3,84.2) v1(32.7,84.2) ; C13.2@25.859,62.976 25.995,62.84 U7.3@25.995,61.143 ; v1(26.4,47.2) 24.8,48.8 22.8,48.8 22.2,49.4 22.2,54.4 ; v1(28.1,95) v1(24.3,95) 24.2,95 v1(24.2,92.9) v1(27.4,92.9) 28.2,92.1 v1(33.1,92.1) v1(33.1,94.4) ; v1(29.7,56.5) 28.3,56.5 27,55.2 27,54.8 26.6,54.4 22.2,54.4 ; JP4.2@37.42,91.06 41.1,91.06 v1(41.3,91) v1(41.3,86.8) ; v1(38.3,86.8) v1(41.3,86.8) ; v1(41.3,-2) v1(41.3,3.6) v1(41.3,8.8) v1(41.3,13.6) v1(41.3,18.8) v1(41.3,23.8) v1(41.3,29) v1(41.3,34) v1(41.3,39) v1(41.3,44.2) v1(41.3,49) v1(41.3,54.4) v1(41.3,59.4) v1(41.3,64.6) v1(41.3,69.2) v1(41.3,72.8) v1(41.3,76) v1(41.3,79.8) v1(41.3,83.8) v1(41.3,86.8) ; -12.3,72.662 D6.1@-11.215,72.662 ; v1@25,36.1 v1@25.1,36 ; v1@25,36.1 v1(25,36) v1@25.1,36
  Top w0.2: C6.1@8.9,84.008 9.092,84.2 10.501,84.2 10.901,83.8 U2.47@10.901,82.389 ; U8.31@17.3,24.8 17.3,25.6
  Top w0.25: C10.1@6,77.808 6.008,77.8 6.339,77.8 6.9,77.239 U2.8@8.751,77.239 ; C18.1@10.408,39.2 10.8,38.808 U8.63@10.8,37.3 ; U8.47@20.3,34.3 21.5,34.3 21.8,34.6 22.592,34.6 22.438,34.594 C20.1@22.4,34.592
  Top w0.3: D5.2@-11.252,81.812 D5.1@-9.347,81.812 -9.347,84.07 -8.916,84.5 v1(-8.8,84.5) ; v1(2.8,4.2) v1(2.8,6.4) ; v1(6.4,4.2) v1(6.4,6.4) ; U5.2@18.645,61.213 18.645,62.112 19.046,62.513 21.325,62.513 21.695,62.143 U6.3@21.695,61.213
  Top w0.4: C9.1@-1.15,79.378 -1.172,79.4 -1.7,79.4 v1(-2.3,78.8) -2.5,78.6 -2.5,77.6 -2.3,77.4 -0.9,77.4 0.9,75.6 3.5,75.6 4.3,76.4 4.3,77.208 4.9,77.808 C10.1@6,77.808 ; U3.8@0.35,64.9 0.345,64.895 0.345,62.631 0.858,62.118 C14.1@6.404,62.118 ; C24.1@3.1,21.492 3.1,19.8 C26.2@4.9,19.8 ; v1(7.3,36.2) 7.9,36.2 8.1,36.4 8.1,37.562 C19.2@8.062,37.6 ; C25.1@9.1,21.892 9.1,16.6 v1(9.4,16.3) ; v1(13.2,28.2) 13.5,28.2 15.7,30.4 15.7,32 19.7,36 v1(20.2,36) ; B2.3@18.923,3.268 18.946,3.245 19,3.191 v1(19,1.4) ; D4.1@21.447,73.709 D4.2@23.352,73.709 ; D3.2@21.548,80.191 D3.1@23.453,80.191 ; v1(21.7,42.6) 22.486,42.6 22.5,42.6 SB3.1@22.7,42.9 ; C20.1@22.4,34.592 22.8,34.594 ; v1(32.7,90) 34.5,90 C4.1@34.5,88.308
  Top w0.5: P1.28@-8.3,-0.38 LD3.2@-3.139,-0.321 -5.4,-0.321 v1(-5,-0.2) ; R38.1@-3.108,10.4 -3.108,20.6 v1(-1.7,20.6) ; v1(11.8,88.7) 12.957,88.7 CN1.5@12.957,89.55 ; B2.3@18.923,3.268 18.935,3.28 28.02,3.28 28.04,3.3 v1(29.9,3.3)
  Top w0.6: P1.9@-8.3,47.88 -9.78,47.88 -10.3,48.4 -10.3,65.1 -9.569,65.831 -9.4,66 -8.64,66 -8.471,65.831 P1.2@-8.3,65.66 ; v1(-2.6,80.3) R11.2@-2.6,81.192 ; C16.2@-1.9,43.562 C16.2@-1.903,43.562 ; C22.1@-1.7,29.708 -5.5,29.708 -5.5,32.401 ; C21.1@-1.7,32.492 -1.689,32.401 -5.5,32.401 ; C8.1@-1.15,81.262 -1.15,81.192 -1.15,80.25 v1(-1.1,80.2) ; v1(0.2,36.3) v1(-2.4,36.3) -5.5,36.3 ; v1(2.5,71.6) 2.508,71.592 R15.1@3.5,71.592 ; C17.2@5.7,43.562 C17.2@5.705,43.562 ; R4.1@5.9,86.608 v1(5.9,87.8) ; R5.1@7.4,86.608 7.4,87.7 v1(7.5,87.8) ; v1(7.5,43.6) 5.895,43.573 C17.2@5.705,43.562 ; v1(7.6,90.3) 9.707,90.3 CN1.8@9.707,89.5 ; v1(7.7,93.3) 9.707,93.3 CN1.11@9.707,94.5 ; C11.1@7.8,71.592 8.892,71.592 v1(8.9,71.6) ; v1(8.1,84) 8.108,84.008 C6.1@8.9,84.008 ; v1(8.3,86.6) 8.308,86.608 R6.1@8.9,86.608 ; v1(9.5,40.4) 9.808,40.4 10.408,39.8 C18.1@10.408,39.2 ; R7.2@10.5,85.592 11.292,85.592 v1(11.3,85.6) ; C12.2@17.8,72.692 17.8,71.9 v1(17.9,71.8) ; B2.3@18.9,3.245 B2.3@18.923,3.268 ; CN1.9@19.407,89.5 v1(20.9,89.5) ; CN1.10@19.407,94.5 v1(21.4,94.5) ; C23.2@20.3,25.008 v1(20.3,25.9) ; v1(20.7,80) 20.9,80.191 D3.2@21.548,80.191 ; v1(21.9,86.6) 21.938,86.562 LD2.2@22.759,86.503 ; 22.806,34.6 v1(23.3,34.6) ; v1(23,21.4) 23,17.8 v1(23.1,17.6) ; D4.2@23.352,73.709 23.753,72.9 v1@23.753,72.452 ; v1(23.7,72.4) v1@23.753,72.452 ; v1(23.8,70.6) 23.753,70.647 23.753,72.4 v1@23.753,72.452 ; v1@24.004,10.9 26.892,10.9 C31.1@26.992,10.8 27,10.792 v1(27,9.2) ; v1(24.1,87.4) 24.138,87.438 C1.1@25.2,87.438 ; v1(24.3,85.6) C5.1@25.238,85.6 ; v1(26.9,87.2) C2.1@26.9,87.992 ; B2.4@28.02,3.28 28.02,1.2 29.541,-0.321 LD4.2@32.141,-0.321 v1@34.707,-0.38 ; v1(29.7,87.8) 29.8,87.8 U1.2@29.8,89.07 ; v1(29.9,3.3) v1(29.9,9.4) ; C3.2@32.7,88.862 v1(32.7,90) ; 34.2,65.1 34.9,65.8 P2.2@37.28,65.8 ; v1(34.707,-0.352) v1@34.707,-0.38 ; P2.28@37.42,-0.38 v1@34.707,-0.38 ; P2.5@37.42,58.04 38.7,58.04 39.7,59 39.7,61.8 39.7,64.4 38.3,65.8 P2.2@37.28,65.8 ; P2.2@37.42,65.66 P2.2@37.28,65.8 ; -5.5,32.401 -5.5,36.3 ; -5.5,36.3 -5.5,43.662 C16.2@-1.903,43.562 ; C16.2@-1.903,43.562 -1.81,43.655 5.613,43.655 C17.2@5.705,43.562
  Top w0.8: LD1.1@-1.7,92.1 v1(0.7,92.1)
  Bottom w0.191: v1(-2.3,23.2) v1(1.9,23.2) ; v1(-1.7,17.4) v1(-1.7,20.6) ; v1(2.5,71.6) v1(0.4,71.6) v1(0.4,73.7) v1(2.9,73.7) ; v1(4.4,28.4) 5.7,28.4 6.5,29.2 6.5,36.2 ; v1(5,88.6) 5,87.1 v1(8.1,84) 8.1,85.487 ; 7.8,17.2 7.8,18.629 7.812,18.641 v1(12,18.641) v1(14.3,18.641) v1(16.6,18.641) ; v1(8,-0.6) 8,1.4 ; v1(8.3,86.6) 8.1,86.4 8.1,85.487 ; v1(12.2,70.6) 12.2,72.611 SB102.1@12.203,72.614 ; v1(12.5,78.3) v1(14.3,80.1) ; v1(20.5,-0.4) v1(23.3,-0.4) v1(27.5,-0.4) ; v1(20.8,85.4) v1@20.983,85.6 ; v1(21.9,86.6) v1@20.983,85.6 ; v1(25,36) 25,44.2 26.4,45.6 v1(26.4,47.2) ; v1(26.9,87.2) 26.7,87.4 v1(24.1,87.4) 24.1,85.6 v1@20.983,85.6 ; 8.1,85.487 8.213,85.6 v1(11.3,85.6) 11.6,85.6 11.6,86.2 13.4,86.2 13.4,85.6 v1@20.983,85.6
  Bottom w0.3: CN2.3@-6.362,80.359 -2.659,80.359 v1(-2.6,80.3) ; v1(-5,-0.2) -5,1.6 -4.2,2.4 -1.8,2.4 -1,3.2 2.8,3.2 v1(2.8,4.2) ; v1(2.8,6.4) v1(6.4,6.4) ; v1(6.4,4.2) 6.4,2.4 7.4,1.4 8,1.4 v1(8.4,1.4)
  Bottom w0.5: v1(8.4,1.4) v1(19,1.4)
  Bottom w0.6: v1(0.2,36.3) 1.3,36.3 1.35,36.25 1.85,36.25 1.9,36.2 6.5,36.2 v1(7.3,36.2) ; v1(2.5,71.6) 2.5,70.8 2.7,70.6 8.5,70.6 8.9,71 v1(8.9,71.6) ; v1(7.5,43.6) 7.5,42.4 v1(9.5,40.4) ; v1(13.2,26.2) v1(13.2,28.2) ; v1(13.9,71.8) v1(15.5,71.8) v1(17.9,71.8) ; v1(17.8,63.3) 21.5,63.3 ; v1(20.2,36) 20.2,36.05 21.1,36.95 22.75,36.95 22.75,41.55 v1(21.7,42.6) ; v1(20.4,3.3) 23.3,3.3 v1(23.3,-0.4) ; SB10.2@20.5,76.12 v1(20.5,77.2) ; 20.9,32 20.9,31.991 ; SB19.1@21.2,32 21.101,31.991 20.9,31.991 ; v1(23,21.4) 22.3,22.1 22.3,23.6 20.3,25.6 v1(20.3,25.9) 20.3,26.6 20.9,27.2 20.9,31.991 ; v1(23.1,17.6) 23.1,11.8 v1(23.9,11) ; v1(23.3,34.6) 21.7,34.6 20.9,33.8 20.9,32.214 20.9,31.991 ; v1(27,9.2) 27.2,9.4 v1(29.9,9.4)
  Bottom w0.8: v1(-10.4,88.8) -8.8,88.8 ; v1(-8.8,84.5) -8.8,88.8 ; JP3.2@-8.3,91.06 -4.3,91.06 -4.3,92.1 ; JP3.1@-8.3,93.6 -4.3,93.6 -4.3,92.1 ; v1(-1.7,17.4) v1(-0.1,17.4) CR1.2@4.4,17.4 ; v1(0.7,88.8) -2.4,88.8 ; v1(0.7,92.1) -2.4,92.1 ; v1(1.6,13.7) 4.7,13.7 CR1.2@4.7,17.2 ; CR1.2@4.5,17.3 CR1.2@4.4,17.4 ; v1(9.4,16.3) 9.4,16.4 7.8,16.4 7.8,17.2 CR1.2@4.7,17.2 ; -8.8,88.8 -2.4,88.8 ; -4.3,92.1 -2.4,92.1 ; -2.4,88.8 -2.4,92.1 ; CR1.2@4.4,17.4 4.7,17.4 4.7,17.3 CR1.2@4.7,17.2
LED_STLINK: R2.1 R3.1 U2.30 | length 30.6
  Top w0.191: R2.1@-3.2,86.092 R3.1@-1.7,86.092 -1.608,86 -0.3,86 v1(0.1,85.6) ; v1(15.3,78.2) 15.839,78.2 16.3,77.739 U2.30@17.551,77.739
  Bottom w0.191: v1(0.1,85.6) 2.7,85.6 4.1,84.2 4.1,76.4 4.5,76 13.1,76 v1(15.3,78.2)
MCO: SB17.2 U2.29 | length 58.2
  Top w0.191: v1(-3.7,44.8) v1(-3.7,48.6) ; v1(15.6,77.2) 17.512,77.2 U2.29@17.551,77.239
  Bottom w0.191: v1(-3.7,44.8) -3.7,41.6 -2.3,40.2 SB17.2@-1.5,40.2 ; v1(-3.7,48.6) -4.1,49 -4.1,70.4 -3.7,70.8 -3.7,74.2 -2.3,75.6 14,75.6 v1(15.6,77.2)
NETB1_1: R36.1 SB4.2 | length 1.8
  Top w0.191: R36.1@-0.962,12 -0.9,12.062 SB4.2@-0.9,13.8
NETB1_2: B1.3 B1.4 C30.2 R36.2 R38.2 | length 19
  Top w0.3: R38.2@-2.092,10.4 -2.092,7.4 0.6,4.708 0.6,3.285 B1.3@0.56,3.245
  Top w0.4: R38.2@-2.092,10.4 C30.2@-0.508,10.4 ; B1.3@0.56,3.245 B1.4@9.66,3.245
NETB2_1: B2.1 B2.2 C31.2 R37.1 SB5.2 | length 15.5
  Top w0.191: R37.1@28,12.2 R37.1@28.008,12.2
  Top w0.2: C31.2@28,10.792 C31.2@28.008,10.8
  Top w0.4: B2.1@18.9,7.745 B2.2@28,7.745 C31.2@28,10.792 ; R37.1@28,12.2 SB5.2@28,14.1 ; C31.2@28.008,10.8 R37.1@28.008,12.2
NETC1_1: C13.1 R18.2 R19.1 | length 3.2
  Top w0.191: R18.2@22.659,64.446 R19.1@24.159,64.446 24.213,64.5 C13.1@25.859,64.5
NETC3_1: C15.1 U3.9 | length 2.3
  Top w0.191: C15.1@-0.4,57.008 0.3,57.708 0.3,58.906 U3.9@0.35,58.956
NETC3_2: C15.2 R23.2 R24.2 | length 2.8
  Top w0.191: C15.2@-0.4,55.992 R23.2@1,55.992 R24.2@2.4,55.992
NETC8_1: C3.1 C4.2 D2.1 U1.5 | length 6.2
  Top w0.3: C3.1@32.7,87.338 32.8,87.338 32.8,87.2 34.4,87.2 C4.2@34.5,87.292
  Top w0.4: U1.5@30.75,86.53 31.828,86.53 32.637,87.338 C3.1@32.7,87.338 ; D2.1@34.5,85.34 C4.2@34.5,87.292
NETC11_2: C5.2 U1.4 | length 2.5
  Top w0.4: C5.2@26.762,85.6 26.97,85.6 27.9,86.53 U1.4@28.85,86.53
NETC16_1: C17.1 SB15.1 U8.3 X2.1 | length 21.7
  Top w0.191: v1(4.9,40.8) 5.3,40.8 5.7,41.2 C17.1@5.7,42.038 5.7,42.138 3.5,42.138 X2.1@3.5,42.05 3.5,39.8 4.9,38.4 4.9,35.6 6.7,33.8 U8.3@7.8,33.8
  Bottom w0.191: SB15.1@-0.4,44.6 -0.301,44.592 1.108,44.592 v1(4.9,40.8)
NETC17_1: C16.1 R28.1 X2.4 | length 7.5
  Top w0.191: R28.1@-0.408,39.4 -1.1,39.4 -1.9,40.2 C16.1@-1.9,42.038 1.112,42.138 X2.4@0.3,42.05
NETC19_2: C22.2 R30.1 X3.1 | length 7.9
  Top w0.191: C22.2@-1.7,28.692 -1.468,28.66 X3.1@1.9,28.66 3.1,28.66 4.527,30.087 5.398,30.087 5.435,30.123 R30.1@5.6,30.238
NETC20_2: C24.2 C26.1 L1.2 U8.13 | length 13.2
  Top w0.191: C26.1@4.929,22.554 C26.1@5.1,22.445 ; 6.276,28.624 6.451,28.8
  Top w0.25: 6.451,28.8 U8.13@7.8,28.8
  Top w0.6: C24.2@3.1,22.508 4.884,22.508 C26.1@4.929,22.554 ; 6.276,28.624 5.9,28.249 5.9,23.6 5.1,22.8 5.1,22.554 C26.1@5.1,22.445 6.307,21.238 L1.2@7.5,21.238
